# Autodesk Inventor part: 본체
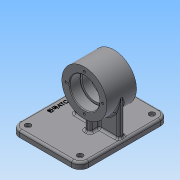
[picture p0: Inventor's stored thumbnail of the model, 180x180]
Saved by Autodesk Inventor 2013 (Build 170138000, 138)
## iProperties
Created: 2019-09
Part Number: 본체
Material: 일반
Document SubType Name: Modeling
Designer: Administrator
Density: 1 g/cm^3
Author: Administrator
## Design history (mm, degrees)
sketch "스케치1"
  geometry: C1 r 32 at (0, 0); 1 further point
  constraints: 1 centre point, 1 coincident
  dimensions: "d0" = 64 diameter of C1
extrude "돌출1" new body sketch "스케치1" stored distance "d1" = 42; taper "d2" = 0 deg
sketch "스케치2"
  geometry: C1 r 32 at (0, 0) reference; C2 r 21 at (0, 0)
  constraints: 1 centre point, 1 coincident
  dimensions: "d3" = 42 diameter of C2
extrude "돌출2" cut sketch "스케치2" distance "d4" = 15; taper "d5" = 0 deg
sketch "스케치3"
  geometry: C1 r 21 at (0, 0) reference; C2 r 18 at (0, 0)
  constraints: 1 centre point, 1 coincident
  dimensions: "d6" = 36 diameter of C2
extrude "돌출3" cut sketch "스케치3" stored distance "d7" = 15; taper "d8" = 0 deg
sketch "스케치4"
  geometry: C1 r 32 at (0, 0) reference; C2 r 21 at (0, 0)
  constraints: 1 centre point, 1 coincident
  dimensions: "d9" = 42 diameter of C2
extrude "돌출4" cut sketch "스케치4" distance "d10" = 15; taper "d11" = 0 deg
fillet "모깎기1" dims "d12" = 0.3
chamfer "모따기1" distance "d13" = 1; stored, may be unused: second distance "d14" = 2, angle "d15" = 45 deg
sketch "스케치5"
  geometry: C1 r 32 at (0, 0) reference; 1 further point
  constraints: 1 vertical alignment
  dimensions: "d16" = 26 distance of point (0, 26) C1.centre
hole "구멍1" sketch "스케치5" at (0, 26) diameter "d17" = 3.242; stored, may be unused: countersink angle "d21" = 90 deg, drill point angle "d23" = 118 deg; dims "d18" = 8, "d19" = 4, "d20" = 2, "d22" = 10
node "작업 평면1"
sketch "스케치6"
  geometry: L1 (62, -63)-(-36, -63); L2 (-36, -63)-(-36, 63); L3 (-36, 63)-(62, 63); L4 (62, 63)-(62, -63); 1 further point
  constraints: 8 end point, 2 parallel, 1 horizontal, 1 perpendicular
  dimensions: "d28" = 98 distance of L2.end L3.end; "d29" = 126 distance of L1.end L2.end; "d31" = 63 distance from line of point (0, 0) L3; "d32" = 62 distance from line of point (0, 0) L4
extrude "돌출5" join sketch "스케치6" distance "d33" = 9; taper "d34" = 0 deg
fillet "모깎기2" dims "d35" = 12
sketch "스케치7"
  geometry: A1 r 12 centre (-50, -51) between (-62, -51) and (-50, -63) reference; A2 r 12 centre (24, -51) between (24, -63) and (36, -51) reference; A3 r 12 centre (24, 51) between (36, 51) and (24, 63) reference; A4 r 12 centre (-50, 51) between (-50, 63) and (-62, 51) reference; 5 further points
  constraints: 4 coincident
hole "구멍2" sketch "스케치7" at (-50, 51), (24, 51), (-50, -51), (24, -51) diameter "d36" = 4.5; stored, may be unused: countersink angle "d40" = 90 deg, drill point angle "d42" = 118 deg; dims "d37" = 8, "d38" = 8, "d39" = 4.4, "d41" = 9
sketch "스케치8"
  geometry: L1 (4, 17)-(-4, 17); L2 (-4, 17)-(-4, -17); L3 (-4, -17)-(4, -17); L4 (4, -17)-(4, 17); L5 (4, 17)-(-4, -17); L6 (-4, 17)-(4, -17); L7 (32, 4)-(-32, 4); L8 (-32, 4)-(-32, -4); L9 (-32, -4)-(32, -4); L10 (32, -4)-(32, 4); L11 (32, 4)-(-32, -4); L12 (-32, 4)-(32, -4); 1 further point
  constraints: 24 end point, 4 midpoint, 4 parallel, 2 horizontal, 2 perpendicular
  dimensions: "d43" = 8 distance of L3.end L2.end; "d44" = 34 distance of L2.end L1.end; "d45" = 64 distance of L9.end L8.end; "d46" = 8 distance of L8.end L7.end
extrude "돌출6" join sketch "스케치8" stored distance "d47" = 9; taper "d48" = 0 deg
sketch "스케치9"
  geometry: L1 (-62, 51)-(-62, -51) reference; 2 further points
  constraints: 1 horizontal alignment, 1 other
  dimensions: "d49" = 10 distance from line of point (-52, 0) L1
feature "엠보싱1" sketch "스케치9" dims "d50" = 0.5, "d51" = 0
fillet "모깎기3" dims "d52" = 3
fillet "모깎기4" dims "d53" = 3
node "솔리드1"
pattern_circular "원형 패턴1" dims angle "d25" = 360 deg
mirror "대칭1"
other parameters: "d27" = -59
